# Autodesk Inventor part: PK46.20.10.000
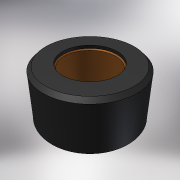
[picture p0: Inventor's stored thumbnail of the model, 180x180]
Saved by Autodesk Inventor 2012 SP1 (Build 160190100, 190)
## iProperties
Created: 2012-02
Part Number: PK46.20.10.000
Material: Silicone
Document SubType Name: Modeling
Designer: tedescj
Density: 1.25 g/cm^3
Author: tedescj
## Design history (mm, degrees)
sketch "Sketch1"
  geometry: C1 r 15 at (-176.079, -140) reference; C2 r 20 at (-176.079, -140); C3 r 11 at (-176.079, -140); C4 r 11.5 at (-176.079, -140)
  constraints: 4 centre point, 2 coincident, 1 concentric, 2 other
  dimensions: "d0" = 40 diameter of C2; "d22" = 22 diameter of C3; "d23" = 0.5 radial gap between concentric circles of C4 C3
extrude "Extrusion1" new body sketch "Sketch1" distance "d1" = 22; taper "d2" = 0 deg
workplane "Work Plane1"
sketch "Sketch2"
  geometry: C1 r 13 at (0, 0); C2 r 11 at (0, 0) reference
  constraints: 1 centre point
  dimensions: "d24" = 2 radial gap between concentric circles of C1 C2
extrude "Extrusion2" new body sketch "Sketch2" stored distance "d9" = 19.5 (computed from d1); taper "d10" = 0 deg
chamfer "Chamfer1" distance "d16" = 1.5; stored, may be unused: second distance "d17" = 2, angle "d18" = 45 deg
chamfer "Chamfer2" distance "d19" = 0.5; stored, may be unused: second distance "d20" = 2, angle "d21" = 45 deg
node "PK46.20.11.000"
node "PK46.20.12.000"
